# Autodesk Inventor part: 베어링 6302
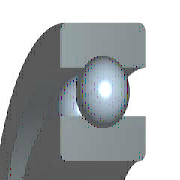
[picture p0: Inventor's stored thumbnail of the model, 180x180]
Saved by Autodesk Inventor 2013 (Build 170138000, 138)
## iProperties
IsCustomPart: 1
Created: 2012-02
Part Number: 베어링 6302
Material: 강철, 연강
Document SubType Name: Modeling
Standard: JIS B 1521
Designer: mdu-01
Standards Organization: JIS
Language: ko-KR
Size Designation: 6302 15x42x13
Categories: <MemberInstance><Categories><Category DisplayName="샤프트 부품" InternalName="7f7aeb1f-a693-4053-b835-cee3144e0d98" Mnemonic="SHFT"><Category DisplayName="베어링" Inter
Density: 1 g/cm^3
Author: mdu-01
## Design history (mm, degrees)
sketch "스케치" dims "d0" = 7.02 (= -0.26 x WD + 0.26 x BD)
  geometry: L1 (2.99, 14.25)-(10.01, 14.25); L2 (6.5, 14.25)-(6.5, 10.74); L3 (6.5, 14.25)-(6.5, 17.76); L4 (3.892, 11.901)-(0, 11.901); L5 (0, 7.5)-(13, 7.5); L6 (3.892, 16.599)-(0, 16.599); L7 (0, 21)-(13, 21); L8 (13, 7.5)-(13, 11.901); L9 (9.108, 11.901)-(13, 11.901); L10 (9.108, 16.599)-(13, 16.599); L11 (13, 21)-(13, 16.599); L12 (-1.4, 0)-(8.4, 0) reference; L13 (0, -0.3)-(0, 5.3) reference
  constraints: 22 end point, 4 point on line, 2 collinear, 2 perpendicular, 2 symmetric about line, 1 midpoint, 1 parallel, 14 other
  dimensions: "d9" = 15 diameter of L5 L12 (= WD); "d11" = 42 diameter of L7 L12 (= BD); "d12" = 13 distance between parallel lines of L8 L13 (= KB); "d13" = 23.802 diameter of L9 L12 (= 0.326 x BD + 0.674 x WD)
revolve "본체" stored, may be unused: angle "d6" = 90 deg
revolve "볼" stored, may be unused: angle "d7" = 90 deg
pattern_circular "IDS_ARRAYBALL[SIMPL:T]" dims angle "d3" = 360 deg
body "Solid1"
fillet "모깎기1" dims "d1" = 1 (= KRS)
other parameters: "WD" = 15 [user parameter; used in 5 equation terms], "BD" = 42 [user parameter; used in 5 equation terms], "KB" = 13 [user parameter; used in 1 equation term], "KRS" = 1 [user parameter; used in 1 equation term], "d4" = 0, "d5" = 0, "d8" = 0, "d14" = 0, "d15" = 0, "BBA" = 0 [user parameter], "BC0" = 5400000 [user parameter], "BC" = 1.14e+07 [user parameter], "BR" = 21 (= 0.5 x BD) [user parameter], "WR" = 7.5 (= 0.5 x WD) [user parameter]
